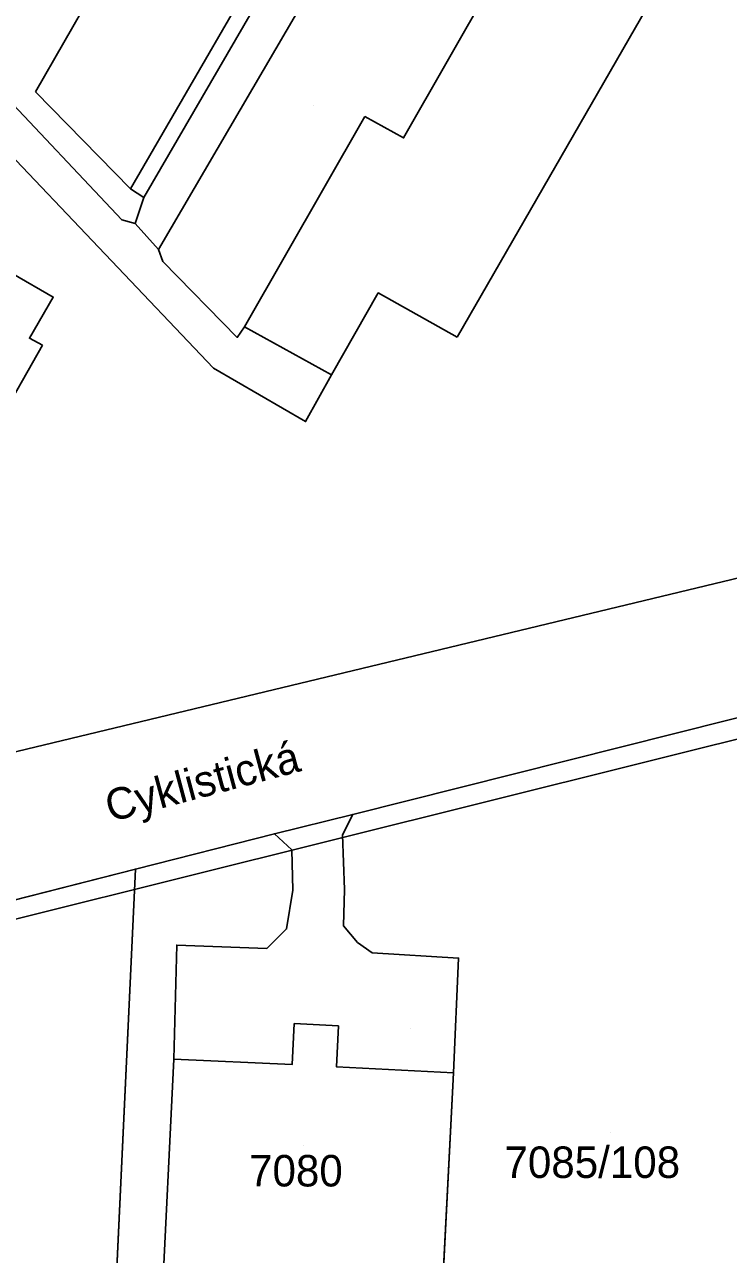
# Model space of a CAD drawing. Extents: x -266199 to -261993, y -1239047 to -1235108.
# Drawn here: x -263730.4 to -263685.7, y -1236679 to -1236600.9 of the extents above; entities that cross this region are included whole.
import ezdxf

# ---------------------------------------------------------------- set-up
doc = ezdxf.new("R2010")
doc.units = 0
for name, color, linetype in [('body_kn', 7, 'Continuous'), ('kladpar_druhypozemkov', 7, 'Continuous'), ('kladpar_hranice', 7, 'Continuous'), ('kladpar_parcelnecisla', 7, 'Continuous'), ('kladpar_plochy', 7, 'Continuous'), ('linie', 7, 'Continuous'), ('popisy', 7, 'Continuous'), ('zappar_hrandruhpozemk', 7, 'Continuous')]:
    doc.layers.add(name, color=color, linetype=linetype)

msp = doc.modelspace()

# ---------------------------------------------------------------- linework, layer by layer
at = {"layer": 'body_kn'}
for p, q in [((-263729.73, -1236605.14), (-263729.73, -1236605.14)), ((-263729.73, -1236605.14), (-263729.73, -1236605.14)), ((-263708.81, -1236606.7), (-263708.81, -1236606.7)), ((-263706.35, -1236608.06), (-263706.35, -1236608.06)), ((-263723.68, -1236611.29), (-263723.68, -1236611.29)), ((-263723.68, -1236611.29), (-263723.68, -1236611.29)), ((-263722.84, -1236611.84), (-263722.84, -1236611.84)), ((-263724.25, -1236613.26), (-263724.25, -1236613.26)), ((-263723.39, -1236613.49), (-263723.39, -1236613.49)), ((-263721.92, -1236615.15), (-263721.92, -1236615.15)), ((-263721.63, -1236615.91), (-263721.63, -1236615.91)), ((-263707.95, -1236617.9), (-263707.95, -1236617.9)), ((-263728.6, -1236618.17), (-263728.6, -1236618.17)), ((-263716.45, -1236620.06), (-263716.45, -1236620.06)), ((-263730.11, -1236620.78), (-263730.11, -1236620.78)), ((-263716.91, -1236620.73), (-263716.91, -1236620.73)), ((-263702.95, -1236620.72), (-263702.95, -1236620.72)), ((-263729.28, -1236621.22), (-263729.28, -1236621.22)), ((-263718.42, -1236622.69), (-263718.42, -1236622.69)), ((-263718.42, -1236622.69), (-263718.42, -1236622.69)), ((-263710.93, -1236623.1), (-263710.93, -1236623.1)), ((-263710.93, -1236623.1), (-263710.93, -1236623.1)), ((-263712.57, -1236626.08), (-263712.57, -1236626.08)), ((-263709.57, -1236651.04), (-263709.57, -1236651.04)), ((-263714.55, -1236652.26), (-263714.55, -1236652.26)), ((-263710.22, -1236652.34), (-263710.22, -1236652.34)), ((-263713.45, -1236653.29), (-263713.45, -1236653.29)), ((-263723.38, -1236654.51), (-263723.38, -1236654.51)), ((-263713.37, -1236655.84), (-263713.37, -1236655.84)), ((-263710.1, -1236655.81), (-263710.1, -1236655.81)), ((-263713.78, -1236658.31), (-263713.78, -1236658.31)), ((-263710.16, -1236658.12), (-263710.16, -1236658.12)), ((-263720.75, -1236659.34), (-263720.75, -1236659.34)), ((-263709.28, -1236659.17), (-263709.28, -1236659.17)), ((-263715.04, -1236659.55), (-263715.04, -1236659.55)), ((-263708.33, -1236659.83), (-263708.33, -1236659.83)), ((-263702.85, -1236660.16), (-263702.85, -1236660.16)), ((-263713.3, -1236664.32), (-263713.3, -1236664.32)), ((-263710.47, -1236664.47), (-263710.47, -1236664.47)), ((-263720.93, -1236666.58), (-263720.93, -1236666.58)), ((-263720.93, -1236666.58), (-263720.93, -1236666.58)), ((-263713.42, -1236666.92), (-263713.42, -1236666.92)), ((-263710.61, -1236667.07), (-263710.61, -1236667.07)), ((-263703.17, -1236667.45), (-263703.17, -1236667.45)), ((-263703.17, -1236667.45), (-263703.17, -1236667.45))]:
    msp.add_line(p, q, dxfattribs=at)
at = {"layer": 'kladpar_druhypozemkov'}
for p, q in [((-263712.07, -1236606.01), (-263712.07, -1236606.01)), ((-263705.92, -1236664.62), (-263705.92, -1236664.62)), ((-263693.2, -1236671.25), (-263693.2, -1236671.25)), ((-263712.71, -1236672.07), (-263712.71, -1236672.07))]:
    msp.add_line(p, q, dxfattribs=at)
at = {"layer": 'kladpar_hranice'}
msp.add_line((-263703.17, -1236667.45), (-263704, -1236683.54), dxfattribs=at)
for points in [[(-263636.73, -1236565.67), (-263652.65, -1236609.13), (-263656.13, -1236613.16), (-263668.82, -1236622.01), (-263669.89, -1236624), (-263672.89, -1236624.8), (-263671.36, -1236630.6), (-263672.4, -1236632.76), (-263674.85, -1236633.55), (-263818.23, -1236668.04)], [(-263818.23, -1236668.04), (-263674.85, -1236633.55), (-263672.4, -1236632.76), (-263671.45, -1236635.78), (-263644.19, -1236628.96), (-263642.35, -1236628.54), (-263601.55, -1236618.12), (-263530.98, -1236600.62)], [(-263529.92, -1236600.16), (-263533.65, -1236606.02), (-263533.22, -1236606.88), (-263549.31, -1236610.77), (-263554.3, -1236612.06), (-263562.93, -1236614.23), (-263587.11, -1236620.29), (-263592.24, -1236621.55), (-263602.18, -1236624.03), (-263624.77, -1236629.66), (-263628.67, -1236630.7), (-263629.53, -1236630.92), (-263641.26, -1236633.86), (-263666.84, -1236640.26), (-263671.97, -1236641.58), (-263682.31, -1236644.18), (-263709.57, -1236651.04), (-263714.55, -1236652.26), (-263723.38, -1236654.51), (-263751.32, -1236661.62)], [(-263704, -1236683.54), (-263703.17, -1236667.45), (-263702.85, -1236660.16), (-263708.33, -1236659.83), (-263709.28, -1236659.17), (-263710.16, -1236658.12), (-263710.1, -1236655.81), (-263710.22, -1236652.34), (-263709.57, -1236651.04), (-263682.31, -1236644.18), (-263684.43, -1236693.45), (-263719.02, -1236701.01)], [(-263721.72, -1236682.63), (-263720.93, -1236666.58), (-263720.75, -1236659.34), (-263715.04, -1236659.55), (-263713.78, -1236658.31), (-263713.37, -1236655.84), (-263713.45, -1236653.29), (-263714.55, -1236652.26), (-263709.57, -1236651.04), (-263710.22, -1236652.34), (-263710.1, -1236655.81), (-263710.16, -1236658.12), (-263709.28, -1236659.17), (-263708.33, -1236659.83), (-263702.85, -1236660.16), (-263703.17, -1236667.45)], [(-263719.02, -1236701.01), (-263725.61, -1236702.46), (-263723.38, -1236654.51), (-263714.55, -1236652.26), (-263713.45, -1236653.29), (-263713.37, -1236655.84), (-263713.78, -1236658.31), (-263715.04, -1236659.55), (-263720.75, -1236659.34), (-263720.93, -1236666.58), (-263721.72, -1236682.63)], [(-263745.73, -1236692.57), (-263744.95, -1236676.65), (-263744.7, -1236669.44), (-263748.86, -1236669.18), (-263749.82, -1236668.85), (-263750.84, -1236667.72), (-263751.37, -1236666.83), (-263751.6, -1236663.28), (-263751.32, -1236661.62), (-263723.38, -1236654.51), (-263725.61, -1236702.46), (-263768.13, -1236711.83)]]:
    msp.add_lwpolyline(points, dxfattribs=at)
at = {"layer": 'kladpar_plochy'}
for p, q in [((-263751.32, -1236661.62), (-263723.38, -1236654.51)), ((-263723.38, -1236654.51), (-263725.61, -1236702.46))]:
    msp.add_line(p, q, dxfattribs=at)
for points in [[(-263636.73, -1236565.67), (-263652.65, -1236609.13), (-263656.13, -1236613.16), (-263668.82, -1236622.01), (-263669.89, -1236624), (-263672.89, -1236624.8), (-263671.36, -1236630.6), (-263672.4, -1236632.76), (-263674.85, -1236633.55), (-263818.23, -1236668.04)], [(-263818.23, -1236668.04), (-263674.85, -1236633.55), (-263672.4, -1236632.76), (-263671.45, -1236635.78), (-263644.19, -1236628.96), (-263642.35, -1236628.54), (-263601.55, -1236618.12), (-263530.98, -1236600.62)], [(-263529.92, -1236600.16), (-263533.65, -1236606.02), (-263533.22, -1236606.88), (-263549.31, -1236610.77), (-263554.3, -1236612.06), (-263562.93, -1236614.23), (-263587.11, -1236620.29), (-263592.24, -1236621.55), (-263602.18, -1236624.03), (-263624.77, -1236629.66), (-263628.67, -1236630.7), (-263629.53, -1236630.92), (-263641.26, -1236633.86), (-263666.84, -1236640.26), (-263671.97, -1236641.58), (-263682.31, -1236644.18), (-263709.57, -1236651.04), (-263714.55, -1236652.26), (-263723.38, -1236654.51), (-263751.32, -1236661.62)], [(-263704, -1236683.54), (-263703.17, -1236667.45), (-263702.85, -1236660.16), (-263708.33, -1236659.83), (-263709.28, -1236659.17), (-263710.16, -1236658.12), (-263710.1, -1236655.81), (-263710.22, -1236652.34), (-263709.57, -1236651.04), (-263682.31, -1236644.18), (-263684.43, -1236693.45)], [(-263721.72, -1236682.63), (-263720.93, -1236666.58), (-263720.75, -1236659.34), (-263715.04, -1236659.55), (-263713.78, -1236658.31), (-263713.37, -1236655.84), (-263713.45, -1236653.29), (-263714.55, -1236652.26), (-263709.57, -1236651.04), (-263710.22, -1236652.34), (-263710.1, -1236655.81), (-263710.16, -1236658.12), (-263709.28, -1236659.17), (-263708.33, -1236659.83), (-263702.85, -1236660.16), (-263703.17, -1236667.45), (-263704, -1236683.54)], [(-263725.61, -1236702.46), (-263723.38, -1236654.51), (-263714.55, -1236652.26), (-263713.45, -1236653.29), (-263713.37, -1236655.84), (-263713.78, -1236658.31), (-263715.04, -1236659.55), (-263720.75, -1236659.34), (-263720.93, -1236666.58), (-263721.72, -1236682.63)]]:
    msp.add_lwpolyline(points, dxfattribs=at)
at = {"layer": 'linie'}
msp.add_lwpolyline([(-263908.36, -1236702.07), (-263845.29, -1236686.31), (-263749.77, -1236662.37), (-263652.33, -1236638.05), (-263553.25, -1236613.22), (-263536.97, -1236609.13), (-263532.95, -1236608.14)], dxfattribs=at)
at = {"layer": 'zappar_hrandruhpozemk'}
for p, q in [((-263723.68, -1236611.29), (-263689.54, -1236552.3)), ((-263688.67, -1236552.98), (-263722.84, -1236611.84)), ((-263687.72, -1236594.27), (-263702.95, -1236620.72)), ((-263739.39, -1236597.21), (-263724.25, -1236613.26)), ((-263723.68, -1236611.29), (-263729.73, -1236605.14)), ((-263718.42, -1236622.69), (-263734.12, -1236606.16)), ((-263716.45, -1236620.06), (-263708.81, -1236606.7)), ((-263724.25, -1236613.26), (-263723.39, -1236613.49)), ((-263710.93, -1236623.1), (-263716.45, -1236620.06)), ((-263741.34, -1236642.47), (-263729.28, -1236621.22)), ((-263713.3, -1236664.32), (-263710.47, -1236664.47))]:
    msp.add_line(p, q, dxfattribs=at)
for points in [[(-263729.73, -1236605.14), (-263717.12, -1236583.16), (-263719.83, -1236581.53)], [(-263700.8, -1236598.34), (-263709.28, -1236593.5), (-263721.92, -1236615.15)], [(-263708.81, -1236606.7), (-263706.35, -1236608.06), (-263700.8, -1236598.34)], [(-263716.45, -1236620.06), (-263716.91, -1236620.73), (-263721.63, -1236615.91), (-263721.92, -1236615.15), (-263723.39, -1236613.49), (-263722.84, -1236611.84), (-263723.68, -1236611.29)], [(-263729.28, -1236621.22), (-263730.11, -1236620.78), (-263728.6, -1236618.17), (-263738.86, -1236612.24)], [(-263702.95, -1236620.72), (-263707.95, -1236617.9), (-263710.93, -1236623.1)], [(-263710.93, -1236623.1), (-263712.57, -1236626.08), (-263718.42, -1236622.69)], [(-263720.93, -1236666.58), (-263713.42, -1236666.92), (-263713.3, -1236664.32)], [(-263710.47, -1236664.47), (-263710.61, -1236667.07), (-263703.17, -1236667.45)]]:
    msp.add_lwpolyline(points, dxfattribs=at)

# ---------------------------------------------------------------- texts
at = {"layer": 'kladpar_parcelnecisla'}
for s, p in [('7080', (-263716.157, -1236674.67)), ('7085/108', (-263699.938, -1236674.13))]:
    msp.add_text(s, height=2, dxfattribs=at).set_placement(p)
at = {"layer": 'popisy'}
msp.add_text('Cyklistická', height=2, rotation=15, dxfattribs=at).set_placement((-263724.973, -1236651.532))

doc.saveas('drawing.dxf')
